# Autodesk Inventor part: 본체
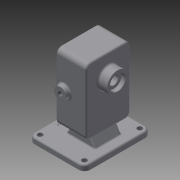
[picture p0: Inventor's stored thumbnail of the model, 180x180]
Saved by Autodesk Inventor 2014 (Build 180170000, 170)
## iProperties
Created: 2020-04
Part Number: 본체
Material: Generic
Document SubType Name: Modeling
Designer: kh
Density: 1 g/cm^3
Appearance: Default
Mass: 544.812 g
Surface Area: 819.925 cm^2
Volume: 544.812 cm^3
Author: kh
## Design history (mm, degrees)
sketch "스케치1"
  geometry: L1 (-50, 60)-(50, 60); L2 (50, 60)-(50, -60); L3 (50, -60)-(-50, -60); L4 (-50, -60)-(-50, 60); L5 (-50, 60)-(50, -60); L6 (50, 60)-(-50, -60); 1 further point
  constraints: 12 end point, 2 midpoint, 2 parallel, 1 horizontal, 1 perpendicular
  dimensions: "d0" = 100 distance of L1.start L1.end; "d1" = 120 distance of L3.end L1.start
extrude "돌출1" new body sketch "스케치1" distance "d2" = 10; taper "d3" = 0 deg
fillet "모깎기1" dims "d7" = 10
sketch "스케치4"
  geometry: A1 r 10 centre (-40, 50) between (-40, 60) and (-50, 50) reference; A2 r 10 centre (40, 50) between (50, 50) and (40, 60) reference; A3 r 10 centre (40, -50) between (40, -60) and (50, -50) reference; A4 r 10 centre (-40, -50) between (-50, -50) and (-40, -60) reference; 1 further point
hole "구멍2" sketch "스케치4" at (-40, -50), (40, -50), (40, 50), (-40, 50) diameter "d17" = 9; stored, may be unused: countersink angle "d21" = 90 deg, drill point angle "d23" = 118 deg; dims "d18" = 6, "d19" = 4, "d20" = 2, "d22" = 8
fillet "모깎기2" dims "d24" = 3
sketch "스케치5"
  geometry: L1 (-33, 150)-(20, 150); L2 (20, 150)-(20, 30); L3 (20, 30)-(-33, 30); L4 (-33, 30)-(-33, 150); L5 (50, 0)-(40, 0) reference; L6 (50, 0)-(50, 7) reference; L7 (-50, 7)-(-50, 0) reference; 2 further points
  constraints: 8 end point, 2 parallel, 1 horizontal, 1 midpoint, 1 perpendicular, 1 vertical alignment
  dimensions: "d25" = 53 distance of L1.start L1.end; "d26" = 120 distance of L3.end L1.start; "d27" = 150 distance between parallel lines of L5 L1; "d114" = 70 distance between parallel lines of L7 L2
extrude "돌출2" join sketch "스케치5" stored distance "d28" = 80; taper "d29" = 0 deg
fillet "모깎기3" dims "d31" = 9
sketch "스케치8"
  geometry: A1 r 9 centre (9, 62) between (9, 71) and (0, 62) reference; A2 r 9 centre (111, 62) between (120, 62) and (111, 71) reference; A3 r 9 centre (111, 0) between (111, -9) and (120, 0) reference; A4 r 9 centre (9, 0) between (0, 0) and (9, -9) reference; 5 further points
  constraints: 4 horizontal alignment, 2 vertical alignment
  dimensions: "d32" = 29 distance of point (82, 62) A2.centre; "d33" = 44 distance of point (38, 62) point (82, 62)
hole "구멍3" sketch "스케치8" at (38, 62), (82, 62), (82, 0), (38, 0), (111, 62), (9, 62), (9, 0), (111, 0) diameter "d34" = 4.459; stored, may be unused: countersink angle "d38" = 90 deg, drill point angle "d40" = 118 deg; dims "d35" = 10, "d36" = 4, "d37" = 2, "d39" = 12
sketch "스케치10"
  geometry: L1 (60, 58.202)-(60, 12); L2 (150, 81)-(150, -19) reference; C1 r 19 at (38, 31); 1 further point
  constraints: 2 end point, 1 centre point, 1 horizontal alignment, 1 vertical
  dimensions: "d41" = 38 diameter of C1; "d56" = 90 distance between parallel lines of L1 L2; "d58" = 22 distance from line of C1.centre L1
extrude "돌출3" join sketch "스케치10" distance "d43" = 17; taper "d44" = 0 deg
sketch "스케치11"
  geometry: C1 r 19 at (0, 0) reference; C2 r 14 at (0, 0); 1 further point
  constraints: 1 centre point, 1 coincident
  dimensions: "d45" = 28 diameter of C2
extrude "돌출4" cut sketch "스케치11" distance "d46" = 7.3; taper "d47" = 0 deg
chamfer "모따기1" distance "d48" = 0.7; stored, may be unused: second distance "d49" = 2, angle "d50" = 30 deg
sketch "스케치14"
  geometry: L1 (38, 31)-(82, 31); L2 (38, 55)-(82, 55); L3 (82, 7)-(38, 7); L4 (49, 79)-(71, 79) reference; L5 (49, 74)-(71, 74) reference; L6 (71, -17)-(49, -17) reference; L7 (71, -12)-(49, -12) reference; L8 (-30, -19)-(-30, 81) reference; A1 r 24 centre (38, 31) between (38, 55) and (38, 7); A2 r 24 centre (82, 31) between (82, 7) and (82, 55); 5 further points
  constraints: 8 end point, 4 midpoint, 4 point on circle, 4 tangent, 2 centre point, 2 vertical alignment, 1 horizontal, 1 horizontal alignment, 1 parallel
  dimensions: "d66" = 24 radius of A2; "d67" = 44 distance of L2.start L2.end
extrude "돌출7" cut sketch "스케치14" distance "d68" = 29; taper "d69" = 0 deg
sketch "스케치15"
  geometry: L1 (38, 55)-(82, 55) reference; L2 (82, 7)-(38, 7) reference; C1 r 12.5 at (82, 31); C2 r 12.5 at (38, 31); A1 r 24 centre (38, 31) between (38, 55) and (38, 7) reference; A2 r 24 centre (82, 31) between (82, 7) and (82, 55) reference; 1 further point
  constraints: 2 centre point, 2 coincident
  dimensions: "d70" = 25 diameter of C1; "d71" = 25 diameter of C2
extrude "돌출8" cut sketch "스케치15" distance "d72" = 15; taper "d73" = 0 deg
sketch "스케치16"
  geometry: C1 r 12.5 at (0, 0) reference; C2 r 8.5 at (0, 0); 1 further point
  constraints: 1 centre point, 1 coincident
  dimensions: "d74" = 17 diameter of C2
extrude "돌출9" cut sketch "스케치16" stored distance "d75" = 15; taper "d76" = 0 deg
fillet "모깎기6" dims "d77" = 0.5
chamfer "모따기2" distance "d78" = 1; stored, may be unused: second distance "d79" = 2, angle "d80" = 30 deg
node "작업 평면4"
sketch "스케치19"
  geometry: L1 (-20, 141)-(-20, 39) reference; L2 (40, 0)-(-40, 0) reference; C1 r 11 at (-6, 90); 1 further point
  constraints: 1 centre point
  dimensions: "d92" = 22 diameter of C1; "d93" = 14 distance from line of C1.centre L1; "d94" = 90 distance from line of L2 C1.centre
extrude "돌출10" join sketch "스케치19" stored distance "d95" = 15; taper "d96" = 0 deg
fillet "모깎기7" dims "d97" = 3
hole "구멍5" diameter "d100" = 8.917; stored, may be unused: countersink angle "d104" = 90 deg, drill point angle "d106" = 118 deg; dims "d98" = 10, "d99" = 10, "d101" = 10, "d102" = 4, "d103" = 2, "d105" = 12
sketch "스케치22"
  geometry: L1 (-41.497, 20.739)-(-41.497, -20.739); L2 (-41.497, -20.739)-(-38.503, -20.739); L3 (-38.503, -20.739)-(-38.503, 20.739); L4 (-38.503, 20.739)-(-41.497, 20.739); L5 (-40, 20.739)-(-40, -20.739); L6 (-38.503, 0)-(-41.497, 0); L7 (40, 60)-(-40, 60) reference; L8 (-50, 50)-(-50, -50) reference; 1 further point
  constraints: 4 end point, 4 midpoint, 2 other
  dimensions: "d117" = 60 distance between parallel lines of L6 L7; "d118" = 10 distance between parallel lines of L5 L8
feature "엠보싱1" sketch "스케치22" dims "d0" = 100, "d1" = 120, "d119" = 0.5, "d120" = 0
sketch "스케치24"
  geometry: L1 (-20, 24)-(33, 24); L2 (33, 24)-(33, -24); L3 (33, -24)-(-20, -24); L4 (-20, -24)-(-20, 24); L5 (50, -50)-(50, 50) reference; 2 further points
  constraints: 8 end point, 2 parallel, 1 horizontal, 1 horizontal alignment, 1 midpoint, 1 perpendicular
  dimensions: "d125" = 17 distance between parallel lines of L2 L5; "d126" = 53 distance of L2.end L3.end; "d127" = 48 distance of L3.end L1.start
extrude "돌출12" join sketch "스케치24" stored distance "d128" = 15; taper "d129" = 0 deg
sketch "스케치25"
  geometry: L1 (53, 0)-(53, 20) reference; L2 (0, 0)-(53, 0) reference; L3 (0, 0)-(0, 20) reference; L4 (53, 20)-(0, 20) reference; L5 (11.547, 20)-(0, 0); L6 (41.453, 20)-(53, 0); L7 (11.547, 20)-(0, 20); L8 (0, 0)-(0, 20); L9 (41.453, 20)-(53, 20); L10 (53, 20)-(53, 0); 1 further point
  constraints: 12 end point, 4 collinear, 2 point on line
  dimensions: "d130" = 60 deg angle of L2 L5; "d131" = 60 deg angle of L2 L6
extrude "돌출13" cut sketch "스케치25" stored distance "d132" = 15; taper "d133" = 0 deg
fillet "모깎기10" dims "d134" = 3
fillet "모깎기11" dims "d135" = 3
node "솔리드1"
mirror "대칭1"
node "투영된 루프1"
node "투영된 루프4"
node "투영된 루프5"
other parameters: "d91" = -48
